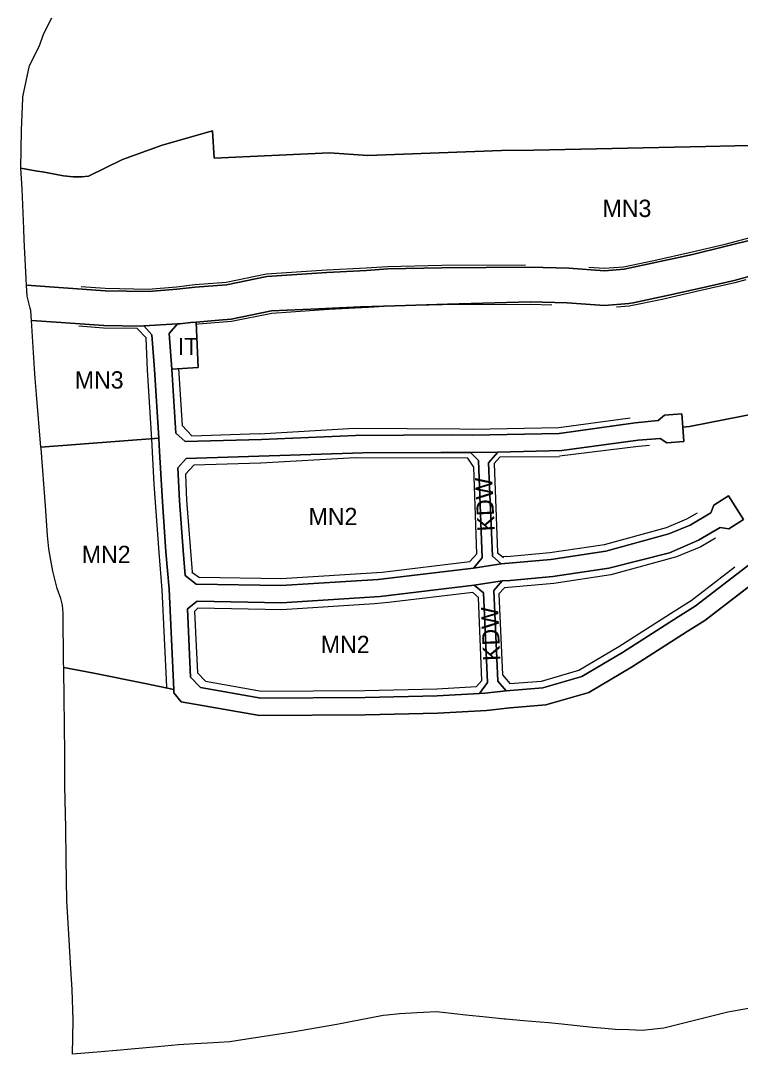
# Model space of a CAD drawing. Extents: x 7417187 to 7419415, y 5539178 to 5540826.
# Drawn here: x 7417414 to 7417830, y 5539408 to 5540006 of the extents above; entities that cross this region are included whole.
import ezdxf

# ---------------------------------------------------------------- set-up
doc = ezdxf.new("R2010")
doc.units = 0
for name, color, linetype in [('linie_rozgraniczajace', 7, 'Continuous'), ('linie_zabudowy_nieprzekraczalne', 7, 'Continuous'), ('oznaczenia_przeznaczen', 7, 'Continuous')]:
    doc.layers.add(name, color=color, linetype=linetype)

msp = doc.modelspace()

# ---------------------------------------------------------------- linework, layer by layer
at = {"layer": 'linie_rozgraniczajace'}
for p, q in [((7417427.9, 5539998.38), (7417432.37, 5540007.43)), ((7417425.1, 5539990.78), (7417427.9, 5539998.38)), ((7417419.46, 5539979.92), (7417425.1, 5539990.78)), ((7417415.74, 5539961.68), (7417419.46, 5539979.92)), ((7417414.86, 5539942.46), (7417415.7, 5539960.75)), ((7417415.7, 5539960.75), (7417415.74, 5539961.68)), ((7417414.43, 5539920.54), (7417414.86, 5539942.46)), ((7417496.23, 5539933.76), (7417525.38, 5539942.03)), ((7417525.38, 5539942.03), (7417496.23, 5539933.76)), ((7417525.38, 5539942.03), (7417526.26, 5539926.3)), ((7417526.26, 5539926.3), (7417525.38, 5539942.03)), ((7417473.39, 5539925.57), (7417496.23, 5539933.76)), ((7417496.23, 5539933.76), (7417473.39, 5539925.57)), ((7417711.14, 5539930.97), (7417810.61, 5539933.08)), ((7417810.61, 5539933.08), (7417711.14, 5539930.97)), ((7417810.61, 5539933.08), (7417851.22, 5539934.03)), ((7417851.22, 5539934.03), (7417810.61, 5539933.08)), ((7417526.26, 5539926.3), (7417593.04, 5539929.37)), ((7417593.04, 5539929.37), (7417526.26, 5539926.3)), ((7417593.04, 5539929.37), (7417615.12, 5539927.87)), ((7417615.12, 5539927.87), (7417593.04, 5539929.37)), ((7417615.12, 5539927.87), (7417692.37, 5539930.82)), ((7417692.37, 5539930.82), (7417615.12, 5539927.87)), ((7417692.37, 5539930.82), (7417711.14, 5539930.97)), ((7417711.14, 5539930.97), (7417692.37, 5539930.82)), ((7417415.36, 5539908.65), (7417414.43, 5539920.54)), ((7417414.43, 5539920.54), (7417423.89, 5539918.86)), ((7417423.89, 5539918.86), (7417414.43, 5539920.54)), ((7417453.56, 5539915.91), (7417473.39, 5539925.57)), ((7417473.39, 5539925.57), (7417453.56, 5539915.91)), ((7417423.89, 5539918.86), (7417427, 5539918.48)), ((7417427, 5539918.48), (7417423.89, 5539918.86)), ((7417427, 5539918.48), (7417439.21, 5539916.01)), ((7417439.21, 5539916.01), (7417427, 5539918.48)), ((7417439.21, 5539916.01), (7417444.86, 5539915.52)), ((7417444.86, 5539915.52), (7417439.21, 5539916.01)), ((7417444.86, 5539915.52), (7417449.57, 5539915.58)), ((7417449.57, 5539915.58), (7417444.86, 5539915.52)), ((7417449.57, 5539915.58), (7417453.56, 5539915.91)), ((7417453.56, 5539915.91), (7417449.57, 5539915.58)), ((7417416.2, 5539885.41), (7417415.36, 5539908.65)), ((7417416.41, 5539879.06), (7417416.2, 5539885.41)), ((7417417.87, 5539852.83), (7417416.41, 5539879.06)), ((7417840.17, 5539879.93), (7417802.91, 5539870.7)), ((7417802.91, 5539870.7), (7417840.17, 5539879.93)), ((7417802.91, 5539870.7), (7417763.22, 5539862.11)), ((7417763.22, 5539862.11), (7417802.91, 5539870.7)), ((7417614.3, 5539861.38), (7417591.37, 5539860.27)), ((7417591.37, 5539860.27), (7417614.3, 5539861.38)), ((7417626.61, 5539862.25), (7417614.3, 5539861.38)), ((7417614.3, 5539861.38), (7417626.61, 5539862.25)), ((7417657.92, 5539862.97), (7417626.61, 5539862.25)), ((7417626.61, 5539862.25), (7417657.92, 5539862.97)), ((7417709.24, 5539863.22), (7417657.92, 5539862.97)), ((7417657.92, 5539862.97), (7417709.24, 5539863.22)), ((7417731.35, 5539862.63), (7417709.24, 5539863.22)), ((7417709.24, 5539863.22), (7417731.35, 5539862.63)), ((7417751.85, 5539861.15), (7417731.35, 5539862.63)), ((7417731.35, 5539862.63), (7417751.85, 5539861.15)), ((7417763.22, 5539862.11), (7417751.85, 5539861.15)), ((7417751.85, 5539861.15), (7417763.22, 5539862.11)), ((7417556.77, 5539857.93), (7417533.37, 5539853.14)), ((7417533.37, 5539853.14), (7417556.77, 5539857.93)), ((7417591.37, 5539860.27), (7417556.77, 5539857.93)), ((7417556.77, 5539857.93), (7417591.37, 5539860.27)), ((7417826.89, 5539855.67), (7417807.37, 5539851.2)), ((7417835.32, 5539857.93), (7417826.89, 5539855.67)), ((7417463.3, 5539849.57), (7417417.87, 5539852.83)), ((7417418.21, 5539846.56), (7417417.87, 5539852.83)), ((7417417.87, 5539852.83), (7417463.3, 5539849.57)), ((7417488.27, 5539849.16), (7417463.3, 5539849.57)), ((7417463.3, 5539849.57), (7417488.27, 5539849.16)), ((7417504.73, 5539850.54), (7417488.27, 5539849.16)), ((7417488.27, 5539849.16), (7417504.73, 5539850.54)), ((7417515.28, 5539851.7), (7417504.73, 5539850.54)), ((7417504.73, 5539850.54), (7417515.28, 5539851.7)), ((7417533.37, 5539853.14), (7417515.28, 5539851.7)), ((7417515.28, 5539851.7), (7417533.37, 5539853.14)), ((7417807.37, 5539851.2), (7417789.08, 5539847.03)), ((7417419.92, 5539839.62), (7417418.21, 5539846.56)), ((7417709.02, 5539843.22), (7417661.18, 5539841.98)), ((7417730.37, 5539842.65), (7417709.02, 5539843.22)), ((7417751.96, 5539841.09), (7417730.37, 5539842.65)), ((7417768.53, 5539842.77), (7417766.04, 5539842.27)), ((7417789.08, 5539847.03), (7417768.53, 5539842.77)), ((7417420.26, 5539838.2), (7417419.92, 5539839.62)), ((7417420.63, 5539832.45), (7417420.26, 5539838.2)), ((7417559.46, 5539838.07), (7417536.18, 5539833.3)), ((7417586.52, 5539839.2), (7417559.46, 5539838.07)), ((7417610.97, 5539840.45), (7417586.52, 5539839.2)), ((7417630.81, 5539840.95), (7417610.97, 5539840.45)), ((7417661.18, 5539841.98), (7417630.81, 5539840.95)), ((7417766.04, 5539842.27), (7417751.96, 5539841.09)), ((7417422.41, 5539804.76), (7417420.63, 5539832.45)), ((7417420.63, 5539832.45), (7417437.81, 5539831.35)), ((7417437.81, 5539831.35), (7417420.63, 5539832.45)), ((7417437.81, 5539831.35), (7417462.42, 5539829.58)), ((7417462.42, 5539829.58), (7417437.81, 5539831.35)), ((7417506.38, 5539830.6), (7417505.16, 5539830.53)), ((7417512.82, 5539831.3), (7417506.38, 5539830.6)), ((7417515.98, 5539831.58), (7417512.82, 5539831.3)), ((7417528.92, 5539832.72), (7417515.98, 5539831.58)), ((7417536.18, 5539833.3), (7417528.92, 5539832.72)), ((7417462.42, 5539829.58), (7417483.93, 5539829.23)), ((7417483.93, 5539829.23), (7417462.42, 5539829.58)), ((7417483.93, 5539829.23), (7417485.54, 5539829.33)), ((7417485.54, 5539829.33), (7417483.93, 5539829.23)), ((7417505.16, 5539830.53), (7417485.54, 5539829.33)), ((7417485.54, 5539829.33), (7417490.34, 5539824.26)), ((7417490.34, 5539824.26), (7417491.74, 5539804.19)), ((7417422.86, 5539798.88), (7417422.41, 5539804.76)), ((7417491.74, 5539804.19), (7417494.25, 5539764.48)), ((7417423.56, 5539789.78), (7417422.86, 5539798.88)), ((7417426.16, 5539759.31), (7417423.56, 5539789.78)), ((7417494.25, 5539764.48), (7417426.16, 5539759.31)), ((7417426.16, 5539759.31), (7417494.25, 5539764.48)), ((7417426.23, 5539758.46), (7417426.16, 5539759.31)), ((7417494.25, 5539764.48), (7417494.73, 5539756.76)), ((7417428.72, 5539725.34), (7417426.23, 5539758.46)), ((7417494.73, 5539756.76), (7417496.34, 5539727.71)), ((7417429.99, 5539708.29), (7417428.72, 5539725.34)), ((7417496.34, 5539727.71), (7417498.39, 5539698.76)), ((7417430.79, 5539700.4), (7417429.99, 5539708.29)), ((7417431.54, 5539696.02), (7417430.79, 5539700.4)), ((7417432.95, 5539687.65), (7417431.54, 5539696.02)), ((7417498.39, 5539698.76), (7417500.24, 5539677.2)), ((7417435.54, 5539677.59), (7417432.95, 5539687.65)), ((7417810.02, 5539659.15), (7417846.75, 5539687.32)), ((7417437.7, 5539671.86), (7417435.54, 5539677.59)), ((7417500.24, 5539677.2), (7417502.92, 5539619.2)), ((7417438.54, 5539667.93), (7417437.7, 5539671.86)), ((7417438.94, 5539663.39), (7417438.54, 5539667.93)), ((7417439.25, 5539634.67), (7417438.94, 5539663.39)), ((7417799.81, 5539652.66), (7417810.02, 5539659.15)), ((7417767.58, 5539632.13), (7417799.81, 5539652.66)), ((7417439.29, 5539631.95), (7417439.25, 5539634.67)), ((7417456.71, 5539628.66), (7417439.29, 5539631.95)), ((7417439.61, 5539613.23), (7417439.29, 5539631.95)), ((7417439.29, 5539631.95), (7417456.71, 5539628.66)), ((7417486.32, 5539622.6), (7417456.71, 5539628.66)), ((7417456.71, 5539628.66), (7417486.32, 5539622.6)), ((7417742.82, 5539617.41), (7417767.58, 5539632.13)), ((7417502.92, 5539619.2), (7417486.32, 5539622.6)), ((7417486.32, 5539622.6), (7417502.92, 5539619.2)), ((7417502.92, 5539619.2), (7417503.01, 5539617.28)), ((7417503.01, 5539617.28), (7417507.26, 5539612.1)), ((7417718.1, 5539610.22), (7417742.82, 5539617.41)), ((7417439.77, 5539599.76), (7417439.61, 5539613.23)), ((7417507.26, 5539612.1), (7417552.42, 5539604.18)), ((7417697.34, 5539608.58), (7417718.1, 5539610.22)), ((7417552.42, 5539604.18), (7417613.65, 5539604.54)), ((7417613.65, 5539604.54), (7417655.6, 5539605.56)), ((7417655.6, 5539605.56), (7417683.64, 5539607.12)), ((7417683.64, 5539607.12), (7417697.34, 5539608.58)), ((7417439.95, 5539580.44), (7417439.77, 5539599.76)), ((7417440.02, 5539563.5), (7417439.95, 5539580.44)), ((7417440.6, 5539539.03), (7417440.02, 5539563.5)), ((7417440.79, 5539521.35), (7417440.6, 5539539.03)), ((7417441.08, 5539497.07), (7417440.79, 5539521.35)), ((7417442.45, 5539474.46), (7417441.08, 5539497.07)), ((7417443.37, 5539457.76), (7417442.45, 5539474.46)), ((7417444.29, 5539445.82), (7417443.37, 5539457.76)), ((7417444.69, 5539428.04), (7417444.29, 5539445.82)), ((7417624.07, 5539430.65), (7417597.25, 5539425.61)), ((7417626.35, 5539430.9), (7417624.07, 5539430.65)), ((7417633.47, 5539431.67), (7417626.35, 5539430.9)), ((7417643.5, 5539432.2), (7417633.47, 5539431.67)), ((7417654.79, 5539432.81), (7417643.5, 5539432.2)), ((7417658.27, 5539432.44), (7417654.79, 5539432.81)), ((7417671.85, 5539430.98), (7417658.27, 5539432.44)), ((7417683.47, 5539429.74), (7417671.85, 5539430.98)), ((7417823.32, 5539432.65), (7417803.26, 5539427.61)), ((7417835.28, 5539434.72), (7417823.32, 5539432.65)), ((7417444.34, 5539408.29), (7417444.69, 5539428.04)), ((7417591.65, 5539424.55), (7417571.66, 5539421)), ((7417597.25, 5539425.61), (7417591.65, 5539424.55)), ((7417694.06, 5539428.61), (7417683.47, 5539429.74)), ((7417694.93, 5539428.52), (7417694.06, 5539428.61)), ((7417705.05, 5539427.71), (7417694.93, 5539428.52)), ((7417719.64, 5539426.54), (7417705.05, 5539427.71)), ((7417727.32, 5539425.7), (7417719.64, 5539426.54)), ((7417744.96, 5539423.77), (7417727.32, 5539425.7)), ((7417803.26, 5539427.61), (7417786.25, 5539423.34)), ((7417571.66, 5539421), (7417548.87, 5539417.56)), ((7417752.23, 5539423.2), (7417744.96, 5539423.77)), ((7417758.03, 5539422.73), (7417752.23, 5539423.2)), ((7417765.92, 5539422.38), (7417758.03, 5539422.73)), ((7417773.64, 5539422.03), (7417765.92, 5539422.38)), ((7417780.83, 5539422.78), (7417773.64, 5539422.03)), ((7417786.25, 5539423.34), (7417780.83, 5539422.78)), ((7417493.46, 5539412.65), (7417478.24, 5539411.29)), ((7417505.76, 5539413.74), (7417493.46, 5539412.65)), ((7417515.2, 5539414.31), (7417505.76, 5539413.74)), ((7417522.43, 5539414.76), (7417515.2, 5539414.31)), ((7417529.01, 5539415.18), (7417522.43, 5539414.76)), ((7417535.32, 5539415.58), (7417529.01, 5539415.18)), ((7417548.87, 5539417.56), (7417535.32, 5539415.58)), ((7417461.01, 5539409.76), (7417444.34, 5539408.29)), ((7417469.54, 5539410.52), (7417461.01, 5539409.76)), ((7417469.96, 5539410.56), (7417469.54, 5539410.52)), ((7417478.24, 5539411.29), (7417469.96, 5539410.56))]:
    msp.add_line(p, q, dxfattribs=at)
for points in [[(7417841.36, 5539779.19), (7417801.05, 5539771.12), (7417797.2, 5539770.74), (7417796.56, 5539778.55), (7417786.57, 5539777.71), (7417783.02, 5539774.63), (7417769.68, 5539773.24), (7417725.82, 5539767.18), (7417675.71, 5539766.13), (7417663.47, 5539766.29), (7417608.09, 5539766.02), (7417553.61, 5539763.77), (7417509.58, 5539762.5), (7417504.09, 5539767.3), (7417501.75, 5539804.43), (7417517.06, 5539805.28), (7417515.98, 5539831.58), (7417528.92, 5539832.72), (7417536.18, 5539833.3), (7417559.46, 5539838.07), (7417586.52, 5539839.2), (7417610.97, 5539840.45), (7417630.81, 5539840.95), (7417661.18, 5539841.98), (7417709.02, 5539843.22), (7417730.37, 5539842.65), (7417751.96, 5539841.09), (7417766.04, 5539842.27), (7417768.53, 5539842.77), (7417789.08, 5539847.03), (7417807.37, 5539851.2), (7417826.89, 5539855.67), (7417835.32, 5539857.93)], [(7417846.75, 5539687.32), (7417810.02, 5539659.15), (7417799.81, 5539652.66), (7417767.58, 5539632.13), (7417742.82, 5539617.41), (7417718.1, 5539610.22), (7417697.34, 5539608.58), (7417683.64, 5539607.12), (7417655.6, 5539605.56), (7417613.65, 5539604.54), (7417552.42, 5539604.18), (7417507.26, 5539612.1), (7417503.01, 5539617.28), (7417502.92, 5539619.2), (7417500.24, 5539677.2), (7417498.39, 5539698.76), (7417496.34, 5539727.71), (7417494.73, 5539756.76), (7417494.25, 5539764.48), (7417491.74, 5539804.19), (7417490.34, 5539824.26), (7417485.54, 5539829.33), (7417505.16, 5539830.53), (7417500.32, 5539824.96), (7417501.75, 5539804.43), (7417504.09, 5539767.3), (7417509.58, 5539762.5), (7417553.61, 5539763.77), (7417608.09, 5539766.02), (7417663.47, 5539766.29), (7417675.71, 5539766.13), (7417725.82, 5539767.18), (7417769.68, 5539773.24), (7417783.02, 5539774.63), (7417786.57, 5539777.71), (7417796.56, 5539778.55), (7417797.2, 5539770.74), (7417797.87, 5539762.52), (7417787.9, 5539761.7), (7417784.14, 5539764.33), (7417771.31, 5539763.37), (7417727.19, 5539757.28), (7417690.28, 5539756.43), (7417674.4, 5539756.17), (7417657.4, 5539756.26), (7417612.22, 5539756.04), (7417510.19, 5539752.77), (7417505.27, 5539747.33), (7417506.32, 5539728.31), (7417508.36, 5539699.55), (7417509.61, 5539685.03), (7417515.98, 5539680.15), (7417565.07, 5539679.25), (7417621.02, 5539682.77), (7417676.3, 5539689.39), (7417692.29, 5539691.9), (7417720.91, 5539694.33), (7417752.73, 5539699.14), (7417789.1, 5539709.09), (7417801.38, 5539714.19), (7417813.42, 5539721.29), (7417815.18, 5539725.73), (7417823.66, 5539731.08), (7417832.22, 5539717.46), (7417823.75, 5539712.14), (7417818.77, 5539712.8), (7417806.28, 5539705.47), (7417789.55, 5539698.12), (7417754.37, 5539689.28), (7417722.11, 5539684.4), (7417697.41, 5539682.2), (7417692.77, 5539681.93), (7417676.52, 5539679.45), (7417622.29, 5539672.85), (7417565.29, 5539669.24), (7417516.54, 5539670.14), (7417510.79, 5539665.72), (7417512.6, 5539626.33), (7417518.34, 5539620.31), (7417553.27, 5539614.19), (7417613.5, 5539614.53), (7417655.2, 5539615.55), (7417679.71, 5539616.91), (7417682.83, 5539617.09), (7417695.13, 5539618.39), (7417716.29, 5539620.11), (7417738.81, 5539626.65), (7417762.34, 5539640.65), (7417794.44, 5539661.09), (7417804.28, 5539667.35), (7417841.69, 5539696.04)], [(7417841.69, 5539696.04), (7417804.28, 5539667.35), (7417794.44, 5539661.09), (7417762.34, 5539640.65), (7417738.81, 5539626.65), (7417716.29, 5539620.11), (7417695.13, 5539618.39), (7417690.25, 5539623.9), (7417687.98, 5539676.31), (7417692.77, 5539681.93), (7417697.41, 5539682.2), (7417722.11, 5539684.4), (7417754.37, 5539689.28), (7417789.55, 5539698.12), (7417806.28, 5539705.47), (7417818.77, 5539712.8), (7417823.75, 5539712.14), (7417832.22, 5539717.46), (7417823.66, 5539731.08), (7417815.18, 5539725.73), (7417813.42, 5539721.29), (7417801.38, 5539714.19), (7417789.1, 5539709.09), (7417752.73, 5539699.14), (7417720.91, 5539694.33), (7417692.29, 5539691.9), (7417687.19, 5539696.32), (7417684.87, 5539750.12), (7417690.28, 5539756.43), (7417727.19, 5539757.28), (7417771.31, 5539763.37), (7417784.14, 5539764.33), (7417787.9, 5539761.7), (7417797.87, 5539762.52), (7417797.2, 5539770.74), (7417801.05, 5539771.12), (7417841.36, 5539779.19)]]:
    msp.add_lwpolyline(points, dxfattribs=at)
for points in [[(7417501.75, 5539804.43), (7417500.32, 5539824.96), (7417505.16, 5539830.53), (7417506.38, 5539830.6), (7417512.82, 5539831.3), (7417515.98, 5539831.58), (7417517.06, 5539805.28)], [(7417674.4, 5539756.17), (7417679.18, 5539751.47), (7417681.26, 5539695.2), (7417676.3, 5539689.39), (7417621.02, 5539682.77), (7417565.07, 5539679.25), (7417515.98, 5539680.15), (7417509.61, 5539685.03), (7417508.36, 5539699.55), (7417506.32, 5539728.31), (7417505.27, 5539747.33), (7417510.19, 5539752.77), (7417612.22, 5539756.04), (7417657.4, 5539756.26)], [(7417692.29, 5539691.9), (7417676.3, 5539689.39), (7417681.26, 5539695.2), (7417679.18, 5539751.47), (7417674.4, 5539756.17), (7417690.28, 5539756.43), (7417684.87, 5539750.12), (7417687.19, 5539696.32)], [(7417695.13, 5539618.39), (7417682.83, 5539617.09), (7417679.71, 5539616.91), (7417684.28, 5539623.15), (7417681.94, 5539675.03), (7417676.52, 5539679.45), (7417692.77, 5539681.93), (7417687.98, 5539676.31), (7417690.25, 5539623.9)], [(7417679.71, 5539616.91), (7417655.2, 5539615.55), (7417613.5, 5539614.53), (7417553.27, 5539614.19), (7417518.34, 5539620.31), (7417512.6, 5539626.33), (7417510.79, 5539665.72), (7417516.54, 5539670.14), (7417565.29, 5539669.24), (7417622.29, 5539672.85), (7417676.52, 5539679.45), (7417681.94, 5539675.03), (7417684.28, 5539623.15)]]:
    msp.add_lwpolyline(points, close=True, dxfattribs=at)
at = {"layer": 'linie_zabudowy_nieprzekraczalne'}
for points in [[(7417742.82, 5539863.31), (7417751.84, 5539862.66), (7417763.01, 5539863.59), (7417780.48, 5539867.12), (7417802.58, 5539872.16), (7417821.71, 5539876.55), (7417839.88, 5539881.41), (7417851.94, 5539883.09), (7417868.79, 5539884.53), (7417889.13, 5539884.98), (7417908.56, 5539884.44), (7417918.49, 5539883.26)], [(7417449.44, 5539852.07), (7417463.37, 5539851.07), (7417488.22, 5539850.67), (7417504.59, 5539852.03), (7417515.14, 5539853.19), (7417533.16, 5539854.63), (7417556.57, 5539859.42), (7417591.29, 5539861.77), (7417614.21, 5539862.88), (7417626.54, 5539863.75), (7417657.9, 5539864.47), (7417706.35, 5539864.71)], [(7417833.56, 5539855.91), (7417827.25, 5539854.22), (7417807.7, 5539849.74), (7417785.31, 5539844.63), (7417766.25, 5539840.79), (7417758.79, 5539840.16)], [(7417721.48, 5539841.39), (7417709.01, 5539841.72), (7417658.22, 5539841.47), (7417627.62, 5539840.77), (7417615.58, 5539839.92), (7417592.62, 5539838.81), (7417559.66, 5539836.58), (7417536.39, 5539831.82), (7417517.31, 5539830.29), (7417516.04, 5539830.15)], [(7417481.8, 5539827.8), (7417462.36, 5539828.08), (7417448.05, 5539829.11)], [(7417487.01, 5539822.53), (7417481.8, 5539827.8)], [(7417487.76, 5539803.8), (7417487.01, 5539822.53)], [(7417490.28, 5539763.85), (7417487.77, 5539803.67)], [(7417505.74, 5539804.76), (7417507.82, 5539771.78)], [(7417505.74, 5539804.65), (7417505.75, 5539804.55)], [(7417507.82, 5539771.78), (7417513.34, 5539765.82)], [(7417668.24, 5539769.83), (7417675.74, 5539769.63), (7417725.5, 5539770.67), (7417766.82, 5539776.25)], [(7417513.34, 5539765.82), (7417552.56, 5539767.06)], [(7417552.35, 5539767.05), (7417607.4, 5539770.17), (7417668.24, 5539769.83)], [(7417491.61, 5539737.93), (7417490.28, 5539763.92)], [(7417771.54, 5539759.67), (7417725.99, 5539754)], [(7417778.02, 5539760.31), (7417771.54, 5539759.67)], [(7417672.95, 5539752.81), (7417607.84, 5539753.17), (7417553.28, 5539750.08)], [(7417691.42, 5539753.39), (7417688.25, 5539749.77)], [(7417726, 5539753.68), (7417691.42, 5539753.39)], [(7417514.61, 5539748.86), (7417509.77, 5539743.65)], [(7417553.13, 5539750.07), (7417514.61, 5539748.86)], [(7417676.32, 5539747.61), (7417672.95, 5539752.81)], [(7417678.17, 5539697.65), (7417676.32, 5539747.61)], [(7417688.25, 5539749.77), (7417690.15, 5539698.41)], [(7417509.77, 5539743.65), (7417510.33, 5539728.39)], [(7417494.41, 5539698.46), (7417491.62, 5539737.81)], [(7417510.32, 5539728.56), (7417513.64, 5539686.94)], [(7417695.51, 5539696.05), (7417720.43, 5539698.31), (7417751.9, 5539703.06), (7417787.8, 5539712.88), (7417799.6, 5539717.78), (7417805.68, 5539721.35)], [(7417816.09, 5539706.59), (7417807.64, 5539701.63), (7417793.65, 5539695.82), (7417755.63, 5539685.43), (7417722.59, 5539680.43), (7417694.13, 5539678.01)], [(7417496.27, 5539676.72), (7417494.41, 5539698.37)], [(7417674.03, 5539693.08), (7417678.17, 5539697.65)], [(7417689.83, 5539698.4), (7417693.48, 5539695.5)], [(7417695.51, 5539696.05), (7417693.44, 5539695.83)], [(7417623.44, 5539687.09), (7417674.03, 5539693.08)], [(7417792.3, 5539664.47), (7417801.99, 5539670.64), (7417827.37, 5539690.1)], [(7417513.32, 5539686.92), (7417517.74, 5539683.82)], [(7417517.75, 5539684.14), (7417564.98, 5539683.25), (7417623.44, 5539687.09)], [(7417498.85, 5539620.63), (7417496.26, 5539676.96)], [(7417675.92, 5539675.32), (7417627, 5539669.38)], [(7417679.16, 5539672.33), (7417675.92, 5539675.32)], [(7417694.13, 5539678.01), (7417690.92, 5539674.44)], [(7417627, 5539669.38), (7417619, 5539668.62)], [(7417681.06, 5539624.46), (7417679.16, 5539672.33)], [(7417690.92, 5539674.44), (7417693.02, 5539627.73)], [(7417516.88, 5539666.2), (7417514.86, 5539664.17)], [(7417514.86, 5539664.17), (7417515.85, 5539644.38)], [(7417619, 5539668.62), (7417565.38, 5539665.24), (7417516.88, 5539666.2)], [(7417697.28, 5539622.72), (7417715.57, 5539624.07), (7417737.2, 5539630.35), (7417760.24, 5539644.06), (7417792.3, 5539664.47)], [(7417515.86, 5539644.34), (7417516.59, 5539628.9)], [(7417516.59, 5539628.9), (7417521.23, 5539624.01)], [(7417693.02, 5539627.73), (7417697.28, 5539622.72)], [(7417521.23, 5539624.01), (7417553.62, 5539618.19)], [(7417678.01, 5539620.85), (7417681.06, 5539624.46)], [(7417553.62, 5539618.19), (7417613.45, 5539618.54), (7417655.04, 5539619.55), (7417678.01, 5539620.85)]]:
    msp.add_lwpolyline(points, dxfattribs=at)
msp.add_arc((7417356.44, 5539610.99), 142.74, 3.62904, 3.87442, dxfattribs=at)

# ---------------------------------------------------------------- texts
at = {"layer": 'oznaczenia_przeznaczen'}
for s, p in [('MN3', (7417750.8, 5539892.3)), ('IT', (7417505.27, 5539812.44)), ('MN3', (7417445.71, 5539793.13)), ('MN2', (7417580.83, 5539714.18)), ('MN2', (7417449.75, 5539692.26)), ('MN2', (7417587.93, 5539640.24))]:
    msp.add_text(s, height=10, dxfattribs=at).set_placement(p)
for rotation, p in [(92.86241, (7417688.56, 5539710.82)), (92.29061, (7417691.73, 5539635.88))]:
    msp.add_text('KDW', height=10, rotation=rotation, dxfattribs=at).set_placement(p)

doc.saveas('drawing.dxf')
